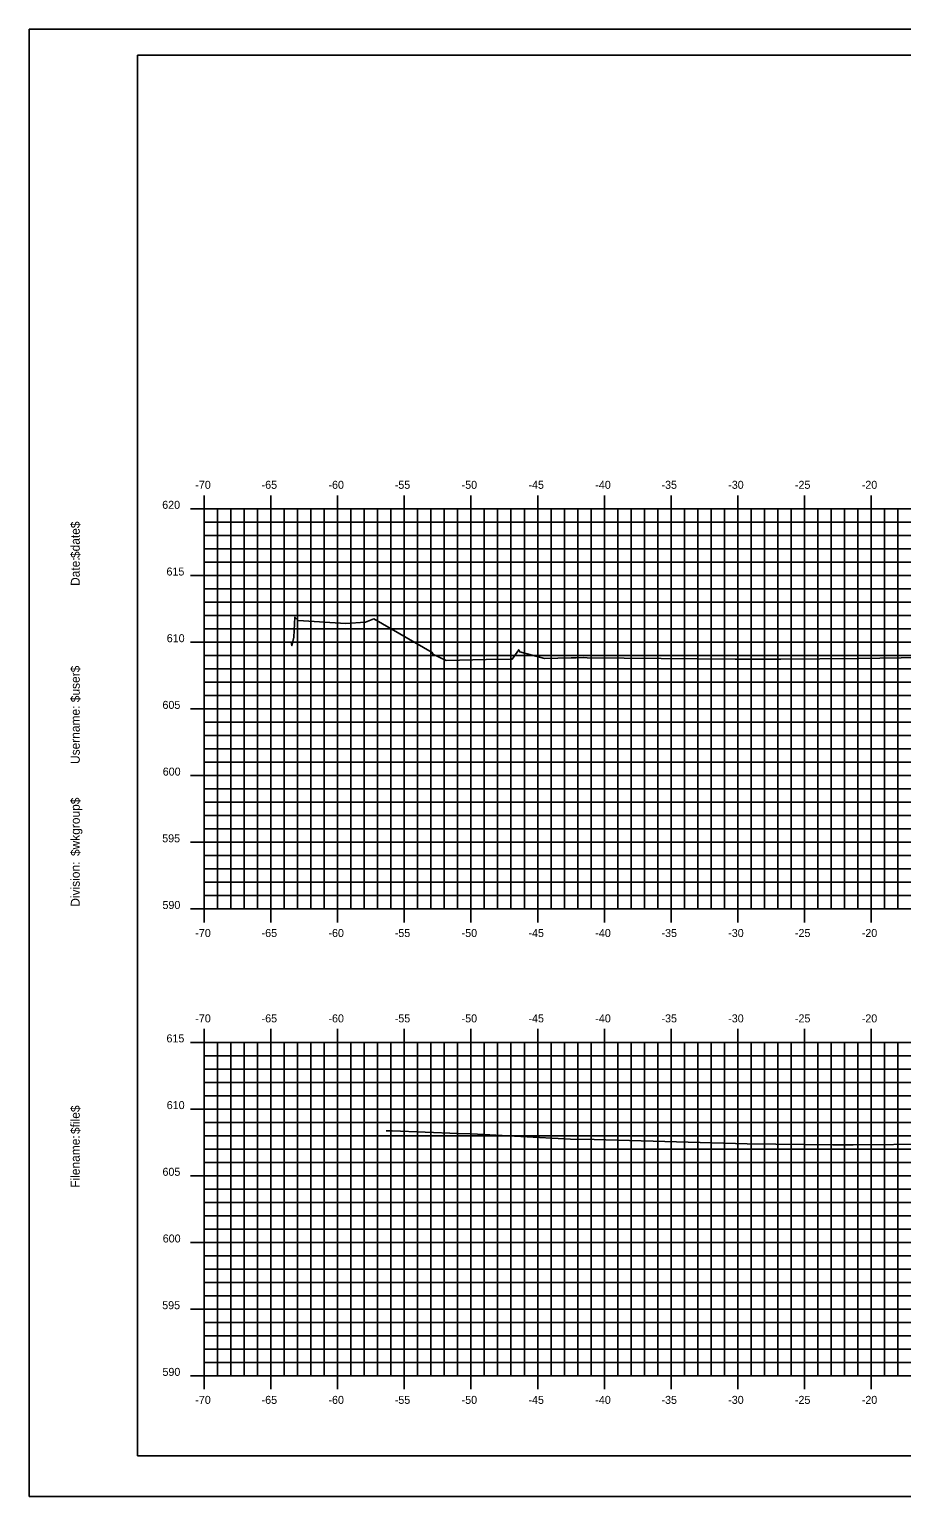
# Model space of a CAD drawing. Extents: x 1048584 to 1048754, y 780904 to 781014.
# Drawn here: x 1048584.1 to 1048649.5, y 780904.1 to 781014.1 of the extents above; entities that cross this region are included whole.
import ezdxf

# ---------------------------------------------------------------- set-up
doc = ezdxf.new("R2010")
doc.units = 0
for name, color, linetype in [('Default', 7, 'Continuous'), ('H_V ANNOTATION', 7, 'Continuous'), ('MAJOR', 7, 'Continuous'), ('MINOR', 7, 'Continuous'), ('S_Roadway_Centerline', 7, 'Continuous')]:
    doc.layers.add(name, color=color, linetype=linetype)

msp = doc.modelspace()

# ---------------------------------------------------------------- linework, layer by layer
at = {"layer": 'Default'}
for p, q in [((1048752.23, 781012.11), (1048592.23, 781012.11)), ((1048592.23, 781012.11), (1048592.23, 780907.11)), ((1048592.23, 780907.11), (1048752.23, 780907.11))]:
    msp.add_line(p, q, dxfattribs=at)
msp.add_lwpolyline([(1048584.13, 780904.06), (1048754.13, 780904.06), (1048754.13, 781014.06), (1048584.13, 781014.06)], close=True, dxfattribs=at)
at = {"layer": 'MAJOR'}
for p, q in [((1048597.23, 780979.12), (1048597.23, 780978.11)), ((1048602.23, 780979.12), (1048602.23, 780978.11)), ((1048607.23, 780979.12), (1048607.23, 780978.11)), ((1048612.23, 780979.12), (1048612.23, 780978.11)), ((1048617.23, 780979.12), (1048617.23, 780978.11)), ((1048622.23, 780979.12), (1048622.23, 780978.11)), ((1048627.23, 780979.12), (1048627.23, 780978.11)), ((1048632.23, 780979.12), (1048632.23, 780978.11)), ((1048637.23, 780979.12), (1048637.23, 780978.11)), ((1048642.23, 780979.12), (1048642.23, 780978.11)), ((1048647.23, 780979.12), (1048647.23, 780978.11)), ((1048596.22, 780978.11), (1048597.23, 780978.11)), ((1048597.23, 780978.11), (1048737.23, 780978.11)), ((1048597.23, 780948.11), (1048597.23, 780978.11)), ((1048597.23, 780948.11), (1048597.23, 780978.11)), ((1048597.23, 780978.11), (1048737.23, 780978.11)), ((1048602.23, 780948.11), (1048602.23, 780978.11)), ((1048607.23, 780948.11), (1048607.23, 780978.11)), ((1048612.23, 780948.11), (1048612.23, 780978.11)), ((1048617.23, 780948.11), (1048617.23, 780978.11)), ((1048622.23, 780948.11), (1048622.23, 780978.11)), ((1048627.23, 780948.11), (1048627.23, 780978.11)), ((1048632.23, 780948.11), (1048632.23, 780978.11)), ((1048637.23, 780948.11), (1048637.23, 780978.11)), ((1048642.23, 780948.11), (1048642.23, 780978.11)), ((1048647.23, 780948.11), (1048647.23, 780978.11)), ((1048596.22, 780973.11), (1048597.23, 780973.11)), ((1048597.23, 780973.11), (1048737.23, 780973.11)), ((1048596.22, 780968.11), (1048597.23, 780968.11)), ((1048597.23, 780968.11), (1048737.23, 780968.11)), ((1048596.22, 780963.11), (1048597.23, 780963.11)), ((1048597.23, 780963.11), (1048737.23, 780963.11)), ((1048596.22, 780958.11), (1048597.23, 780958.11)), ((1048597.23, 780958.11), (1048737.23, 780958.11)), ((1048596.22, 780953.11), (1048597.23, 780953.11)), ((1048597.23, 780953.11), (1048737.23, 780953.11)), ((1048596.22, 780948.11), (1048597.23, 780948.11)), ((1048597.23, 780948.11), (1048737.23, 780948.11)), ((1048597.23, 780948.11), (1048737.23, 780948.11)), ((1048597.23, 780947.11), (1048597.23, 780948.11)), ((1048602.23, 780947.11), (1048602.23, 780948.11)), ((1048607.23, 780947.11), (1048607.23, 780948.11)), ((1048612.23, 780947.11), (1048612.23, 780948.11)), ((1048617.23, 780947.11), (1048617.23, 780948.11)), ((1048622.23, 780947.11), (1048622.23, 780948.11)), ((1048627.23, 780947.11), (1048627.23, 780948.11)), ((1048632.23, 780947.11), (1048632.23, 780948.11)), ((1048637.23, 780947.11), (1048637.23, 780948.11)), ((1048642.23, 780947.11), (1048642.23, 780948.11)), ((1048647.23, 780947.11), (1048647.23, 780948.11)), ((1048597.23, 780939.12), (1048597.23, 780938.11)), ((1048602.23, 780939.12), (1048602.23, 780938.11)), ((1048607.23, 780939.12), (1048607.23, 780938.11)), ((1048612.23, 780939.12), (1048612.23, 780938.11)), ((1048617.23, 780939.12), (1048617.23, 780938.11)), ((1048622.23, 780939.12), (1048622.23, 780938.11)), ((1048627.23, 780939.12), (1048627.23, 780938.11)), ((1048632.23, 780939.12), (1048632.23, 780938.11)), ((1048637.23, 780939.12), (1048637.23, 780938.11)), ((1048642.23, 780939.12), (1048642.23, 780938.11)), ((1048647.23, 780939.12), (1048647.23, 780938.11)), ((1048596.22, 780938.11), (1048597.23, 780938.11)), ((1048597.23, 780938.11), (1048737.23, 780938.11)), ((1048597.23, 780913.11), (1048597.23, 780938.11)), ((1048597.23, 780913.11), (1048597.23, 780938.11)), ((1048597.23, 780938.11), (1048737.23, 780938.11)), ((1048602.23, 780913.11), (1048602.23, 780938.11)), ((1048607.23, 780913.11), (1048607.23, 780938.11)), ((1048612.23, 780913.11), (1048612.23, 780938.11)), ((1048617.23, 780913.11), (1048617.23, 780938.11)), ((1048622.23, 780913.11), (1048622.23, 780938.11)), ((1048627.23, 780913.11), (1048627.23, 780938.11)), ((1048632.23, 780913.11), (1048632.23, 780938.11)), ((1048637.23, 780913.11), (1048637.23, 780938.11)), ((1048642.23, 780913.11), (1048642.23, 780938.11)), ((1048647.23, 780913.11), (1048647.23, 780938.11)), ((1048596.22, 780933.11), (1048597.23, 780933.11)), ((1048597.23, 780933.11), (1048737.23, 780933.11)), ((1048596.22, 780928.11), (1048597.23, 780928.11)), ((1048597.23, 780928.11), (1048737.23, 780928.11)), ((1048596.22, 780923.11), (1048597.23, 780923.11)), ((1048597.23, 780923.11), (1048737.23, 780923.11)), ((1048596.22, 780918.11), (1048597.23, 780918.11)), ((1048597.23, 780918.11), (1048737.23, 780918.11)), ((1048596.22, 780913.11), (1048597.23, 780913.11)), ((1048597.23, 780913.11), (1048737.23, 780913.11)), ((1048597.23, 780913.11), (1048737.23, 780913.11)), ((1048597.23, 780912.11), (1048597.23, 780913.11)), ((1048602.23, 780912.11), (1048602.23, 780913.11)), ((1048607.23, 780912.11), (1048607.23, 780913.11)), ((1048612.23, 780912.11), (1048612.23, 780913.11)), ((1048617.23, 780912.11), (1048617.23, 780913.11)), ((1048622.23, 780912.11), (1048622.23, 780913.11)), ((1048627.23, 780912.11), (1048627.23, 780913.11)), ((1048632.23, 780912.11), (1048632.23, 780913.11)), ((1048637.23, 780912.11), (1048637.23, 780913.11)), ((1048642.23, 780912.11), (1048642.23, 780913.11)), ((1048647.23, 780912.11), (1048647.23, 780913.11))]:
    msp.add_line(p, q, dxfattribs=at)
at = {"layer": 'MINOR'}
for p, q in [((1048598.23, 780948.11), (1048598.23, 780978.11)), ((1048599.23, 780948.11), (1048599.23, 780978.11)), ((1048600.23, 780948.11), (1048600.23, 780978.11)), ((1048601.23, 780948.11), (1048601.23, 780978.11)), ((1048603.23, 780948.11), (1048603.23, 780978.11)), ((1048604.23, 780948.11), (1048604.23, 780978.11)), ((1048605.23, 780948.11), (1048605.23, 780978.11)), ((1048606.23, 780948.11), (1048606.23, 780978.11)), ((1048608.23, 780948.11), (1048608.23, 780978.11)), ((1048609.23, 780948.11), (1048609.23, 780978.11)), ((1048610.23, 780948.11), (1048610.23, 780978.11)), ((1048611.23, 780948.11), (1048611.23, 780978.11)), ((1048613.23, 780948.11), (1048613.23, 780978.11)), ((1048614.23, 780948.11), (1048614.23, 780978.11)), ((1048615.23, 780948.11), (1048615.23, 780978.11)), ((1048616.23, 780948.11), (1048616.23, 780978.11)), ((1048618.23, 780948.11), (1048618.23, 780978.11)), ((1048619.23, 780948.11), (1048619.23, 780978.11)), ((1048620.23, 780948.11), (1048620.23, 780978.11)), ((1048621.23, 780948.11), (1048621.23, 780978.11)), ((1048623.23, 780948.11), (1048623.23, 780978.11)), ((1048624.23, 780948.11), (1048624.23, 780978.11)), ((1048625.23, 780948.11), (1048625.23, 780978.11)), ((1048626.23, 780948.11), (1048626.23, 780978.11)), ((1048628.23, 780948.11), (1048628.23, 780978.11)), ((1048629.23, 780948.11), (1048629.23, 780978.11)), ((1048630.23, 780948.11), (1048630.23, 780978.11)), ((1048631.23, 780948.11), (1048631.23, 780978.11)), ((1048633.23, 780948.11), (1048633.23, 780978.11)), ((1048634.23, 780948.11), (1048634.23, 780978.11)), ((1048635.23, 780948.11), (1048635.23, 780978.11)), ((1048636.23, 780948.11), (1048636.23, 780978.11)), ((1048638.23, 780948.11), (1048638.23, 780978.11)), ((1048639.23, 780948.11), (1048639.23, 780978.11)), ((1048640.23, 780948.11), (1048640.23, 780978.11)), ((1048641.23, 780948.11), (1048641.23, 780978.11)), ((1048643.23, 780948.11), (1048643.23, 780978.11)), ((1048644.23, 780948.11), (1048644.23, 780978.11)), ((1048645.23, 780948.11), (1048645.23, 780978.11)), ((1048646.23, 780948.11), (1048646.23, 780978.11)), ((1048648.23, 780948.11), (1048648.23, 780978.11)), ((1048649.23, 780948.11), (1048649.23, 780978.11)), ((1048597.23, 780977.11), (1048737.23, 780977.11)), ((1048597.23, 780977.11), (1048598.23, 780977.11)), ((1048597.23, 780976.11), (1048737.23, 780976.11)), ((1048597.23, 780976.11), (1048598.23, 780976.11)), ((1048597.23, 780975.11), (1048737.23, 780975.11)), ((1048597.23, 780975.11), (1048598.23, 780975.11)), ((1048597.23, 780974.11), (1048737.23, 780974.11)), ((1048597.23, 780974.11), (1048598.23, 780974.11)), ((1048597.23, 780972.11), (1048737.23, 780972.11)), ((1048597.23, 780972.11), (1048598.23, 780972.11)), ((1048597.23, 780971.11), (1048737.23, 780971.11)), ((1048597.23, 780971.11), (1048598.23, 780971.11)), ((1048597.23, 780970.11), (1048737.23, 780970.11)), ((1048597.23, 780970.11), (1048598.23, 780970.11)), ((1048597.23, 780969.11), (1048737.23, 780969.11)), ((1048597.23, 780969.11), (1048598.23, 780969.11)), ((1048597.23, 780967.11), (1048737.23, 780967.11)), ((1048597.23, 780967.11), (1048598.23, 780967.11)), ((1048597.23, 780966.11), (1048737.23, 780966.11)), ((1048597.23, 780966.11), (1048598.23, 780966.11)), ((1048597.23, 780965.11), (1048737.23, 780965.11)), ((1048597.23, 780965.11), (1048598.23, 780965.11)), ((1048597.23, 780964.11), (1048737.23, 780964.11)), ((1048597.23, 780964.11), (1048598.23, 780964.11)), ((1048597.23, 780962.11), (1048737.23, 780962.11)), ((1048597.23, 780962.11), (1048598.23, 780962.11)), ((1048597.23, 780961.11), (1048737.23, 780961.11)), ((1048597.23, 780961.11), (1048598.23, 780961.11)), ((1048597.23, 780960.11), (1048737.23, 780960.11)), ((1048597.23, 780960.11), (1048598.23, 780960.11)), ((1048597.23, 780959.11), (1048737.23, 780959.11)), ((1048597.23, 780959.11), (1048598.23, 780959.11)), ((1048597.23, 780957.11), (1048737.23, 780957.11)), ((1048597.23, 780957.11), (1048598.23, 780957.11)), ((1048597.23, 780956.11), (1048737.23, 780956.11)), ((1048597.23, 780956.11), (1048598.23, 780956.11)), ((1048597.23, 780955.11), (1048737.23, 780955.11)), ((1048597.23, 780955.11), (1048598.23, 780955.11)), ((1048597.23, 780954.11), (1048737.23, 780954.11)), ((1048597.23, 780954.11), (1048598.23, 780954.11)), ((1048597.23, 780952.11), (1048737.23, 780952.11)), ((1048597.23, 780952.11), (1048598.23, 780952.11)), ((1048597.23, 780951.11), (1048737.23, 780951.11)), ((1048597.23, 780951.11), (1048598.23, 780951.11)), ((1048597.23, 780950.11), (1048737.23, 780950.11)), ((1048597.23, 780950.11), (1048598.23, 780950.11)), ((1048597.23, 780949.11), (1048737.23, 780949.11)), ((1048597.23, 780949.11), (1048598.23, 780949.11)), ((1048598.23, 780913.11), (1048598.23, 780938.11)), ((1048599.23, 780913.11), (1048599.23, 780938.11)), ((1048600.23, 780913.11), (1048600.23, 780938.11)), ((1048601.23, 780913.11), (1048601.23, 780938.11)), ((1048603.23, 780913.11), (1048603.23, 780938.11)), ((1048604.23, 780913.11), (1048604.23, 780938.11)), ((1048605.23, 780913.11), (1048605.23, 780938.11)), ((1048606.23, 780913.11), (1048606.23, 780938.11)), ((1048608.23, 780913.11), (1048608.23, 780938.11)), ((1048609.23, 780913.11), (1048609.23, 780938.11)), ((1048610.23, 780913.11), (1048610.23, 780938.11)), ((1048611.23, 780913.11), (1048611.23, 780938.11)), ((1048613.23, 780913.11), (1048613.23, 780938.11)), ((1048614.23, 780913.11), (1048614.23, 780938.11)), ((1048615.23, 780913.11), (1048615.23, 780938.11)), ((1048616.23, 780913.11), (1048616.23, 780938.11)), ((1048618.23, 780913.11), (1048618.23, 780938.11)), ((1048619.23, 780913.11), (1048619.23, 780938.11)), ((1048620.23, 780913.11), (1048620.23, 780938.11)), ((1048621.23, 780913.11), (1048621.23, 780938.11)), ((1048623.23, 780913.11), (1048623.23, 780938.11)), ((1048624.23, 780913.11), (1048624.23, 780938.11)), ((1048625.23, 780913.11), (1048625.23, 780938.11)), ((1048626.23, 780913.11), (1048626.23, 780938.11)), ((1048628.23, 780913.11), (1048628.23, 780938.11)), ((1048629.23, 780913.11), (1048629.23, 780938.11)), ((1048630.23, 780913.11), (1048630.23, 780938.11)), ((1048631.23, 780913.11), (1048631.23, 780938.11)), ((1048633.23, 780913.11), (1048633.23, 780938.11)), ((1048634.23, 780913.11), (1048634.23, 780938.11)), ((1048635.23, 780913.11), (1048635.23, 780938.11)), ((1048636.23, 780913.11), (1048636.23, 780938.11)), ((1048638.23, 780913.11), (1048638.23, 780938.11)), ((1048639.23, 780913.11), (1048639.23, 780938.11)), ((1048640.23, 780913.11), (1048640.23, 780938.11)), ((1048641.23, 780913.11), (1048641.23, 780938.11)), ((1048643.23, 780913.11), (1048643.23, 780938.11)), ((1048644.23, 780913.11), (1048644.23, 780938.11)), ((1048645.23, 780913.11), (1048645.23, 780938.11)), ((1048646.23, 780913.11), (1048646.23, 780938.11)), ((1048648.23, 780913.11), (1048648.23, 780938.11)), ((1048649.23, 780913.11), (1048649.23, 780938.11)), ((1048597.23, 780937.11), (1048737.23, 780937.11)), ((1048597.23, 780937.11), (1048598.23, 780937.11)), ((1048597.23, 780936.11), (1048737.23, 780936.11)), ((1048597.23, 780936.11), (1048598.23, 780936.11)), ((1048597.23, 780935.11), (1048737.23, 780935.11)), ((1048597.23, 780935.11), (1048598.23, 780935.11)), ((1048597.23, 780934.11), (1048737.23, 780934.11)), ((1048597.23, 780934.11), (1048598.23, 780934.11)), ((1048597.23, 780932.11), (1048737.23, 780932.11)), ((1048597.23, 780932.11), (1048598.23, 780932.11)), ((1048597.23, 780931.11), (1048737.23, 780931.11)), ((1048597.23, 780931.11), (1048598.23, 780931.11)), ((1048597.23, 780930.11), (1048737.23, 780930.11)), ((1048597.23, 780930.11), (1048598.23, 780930.11)), ((1048597.23, 780929.11), (1048737.23, 780929.11)), ((1048597.23, 780929.11), (1048598.23, 780929.11)), ((1048597.23, 780927.11), (1048737.23, 780927.11)), ((1048597.23, 780927.11), (1048598.23, 780927.11)), ((1048597.23, 780926.11), (1048737.23, 780926.11)), ((1048597.23, 780926.11), (1048598.23, 780926.11)), ((1048597.23, 780925.11), (1048737.23, 780925.11)), ((1048597.23, 780925.11), (1048598.23, 780925.11)), ((1048597.23, 780924.11), (1048737.23, 780924.11)), ((1048597.23, 780924.11), (1048598.23, 780924.11)), ((1048597.23, 780922.11), (1048737.23, 780922.11)), ((1048597.23, 780922.11), (1048598.23, 780922.11)), ((1048597.23, 780921.11), (1048737.23, 780921.11)), ((1048597.23, 780921.11), (1048598.23, 780921.11)), ((1048597.23, 780920.11), (1048737.23, 780920.11)), ((1048597.23, 780920.11), (1048598.23, 780920.11)), ((1048597.23, 780919.11), (1048737.23, 780919.11)), ((1048597.23, 780919.11), (1048598.23, 780919.11)), ((1048597.23, 780917.11), (1048737.23, 780917.11)), ((1048597.23, 780917.11), (1048598.23, 780917.11)), ((1048597.23, 780916.11), (1048737.23, 780916.11)), ((1048597.23, 780916.11), (1048598.23, 780916.11)), ((1048597.23, 780915.11), (1048737.23, 780915.11)), ((1048597.23, 780915.11), (1048598.23, 780915.11)), ((1048597.23, 780914.11), (1048737.23, 780914.11)), ((1048597.23, 780914.11), (1048598.23, 780914.11))]:
    msp.add_line(p, q, dxfattribs=at)
at = {"layer": 'S_Roadway_Centerline'}
for points in [[(1048603.76, 780968.15), (1048603.81, 780967.85), (1048603.95, 780968.49), (1048604.03, 780970), (1048604.28, 780969.75), (1048607.86, 780969.52), (1048609.32, 780969.61), (1048609.96, 780969.86), (1048614.33, 780967.35), (1048614.37, 780967.22), (1048615.37, 780966.74), (1048618.36, 780966.82), (1048620.33, 780966.85), (1048620.81, 780967.54), (1048620.89, 780967.39), (1048622.73, 780966.89), (1048624.75, 780966.94), (1048625.11, 780966.95), (1048625.7, 780966.96), (1048625.94, 780966.95), (1048637.03, 780966.84), (1048640.45, 780966.84), (1048646.3, 780966.89), (1048651.04, 780966.97)], [(1048610.88, 780931.48), (1048610.96, 780931.49), (1048611.33, 780931.48), (1048616.27, 780931.27), (1048617.25, 780931.25), (1048624.7, 780930.86), (1048626.47, 780930.82), (1048637.92, 780930.5), (1048644.36, 780930.44), (1048645.88, 780930.44), (1048651.95, 780930.48)]]:
    msp.add_lwpolyline(points, dxfattribs=at)

# ---------------------------------------------------------------- texts
at = {"layer": 'Default'}
for s, p in [('$date$', (1048587.91, 780974.42)), ('Date:', (1048587.91, 780972.33)), ('$user$', (1048587.91, 780963.61)), ('Username:', (1048587.91, 780958.98)), ('$wkgroup$', (1048587.91, 780952.08)), ('Division:', (1048587.91, 780948.28)), ('$file$', (1048587.91, 780931.24)), ('Filename:', (1048587.91, 780927.21))]:
    msp.add_text(s, height=0.67, rotation=90, dxfattribs=at).set_placement(p)
at = {"layer": 'H_V ANNOTATION'}
for s, p in [('-70', (1048596.57, 780979.61)), ('-65', (1048601.54, 780979.61)), ('-60', (1048606.55, 780979.61)), ('-55', (1048611.52, 780979.61)), ('-50', (1048616.53, 780979.61)), ('-45', (1048621.54, 780979.61)), ('-40', (1048626.55, 780979.61)), ('-35', (1048631.51, 780979.61)), ('-30', (1048636.51, 780979.61)), ('-25', (1048641.51, 780979.61)), ('-20', (1048646.52, 780979.61)), ('620', (1048594.09, 780978.11)), ('615', (1048594.41, 780973.11)), ('610', (1048594.43, 780968.11)), ('605', (1048594.11, 780963.11)), ('600', (1048594.13, 780958.11)), ('595', (1048594.09, 780953.11)), ('590', (1048594.11, 780948.11)), ('-70', (1048596.57, 780946.01)), ('-65', (1048601.54, 780946.01)), ('-60', (1048606.55, 780946.01)), ('-55', (1048611.52, 780946.01)), ('-50', (1048616.53, 780946.01)), ('-45', (1048621.54, 780946.01)), ('-40', (1048626.55, 780946.01)), ('-35', (1048631.51, 780946.01)), ('-30', (1048636.51, 780946.01)), ('-25', (1048641.51, 780946.01)), ('-20', (1048646.52, 780946.01)), ('-70', (1048596.57, 780939.61)), ('-65', (1048601.54, 780939.61)), ('-60', (1048606.55, 780939.61)), ('-55', (1048611.52, 780939.61)), ('-50', (1048616.53, 780939.61)), ('-45', (1048621.54, 780939.61)), ('-40', (1048626.55, 780939.61)), ('-35', (1048631.51, 780939.61)), ('-30', (1048636.51, 780939.61)), ('-25', (1048641.51, 780939.61)), ('-20', (1048646.52, 780939.61)), ('615', (1048594.41, 780938.11)), ('610', (1048594.43, 780933.11)), ('605', (1048594.11, 780928.11)), ('600', (1048594.13, 780923.11)), ('595', (1048594.09, 780918.11)), ('590', (1048594.11, 780913.11)), ('-70', (1048596.57, 780911.01)), ('-65', (1048601.54, 780911.01)), ('-60', (1048606.55, 780911.01)), ('-55', (1048611.52, 780911.01)), ('-50', (1048616.53, 780911.01)), ('-45', (1048621.54, 780911.01)), ('-40', (1048626.55, 780911.01)), ('-35', (1048631.51, 780911.01)), ('-30', (1048636.51, 780911.01)), ('-25', (1048641.51, 780911.01)), ('-20', (1048646.52, 780911.01))]:
    msp.add_text(s, height=0.6, dxfattribs=at).set_placement(p)
at = {"layer": 'MAJOR'}
for p in [(1048597.22, 780948.11), (1048597.22, 780913.11)]:
    msp.add_text('-', height=0.006, dxfattribs=at).set_placement(p)

doc.saveas('drawing.dxf')
